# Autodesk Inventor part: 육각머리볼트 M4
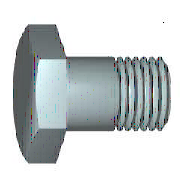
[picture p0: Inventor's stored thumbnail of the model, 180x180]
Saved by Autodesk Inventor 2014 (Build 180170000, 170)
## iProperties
IsCustomPart: 1
Created: 2012-02
Part Number: 육각머리볼트 M4
Material: 강철, 연강
Description: 6각 머리 볼트 및 6각 머리 나사
Document SubType Name: Modeling
Standard: KS B 1002
Designer: mduedu
Standards Organization: KS
Language: ko-KR
Size Designation: A + B M4 x 16
Categories: <MemberInstance><Categories><Category DisplayName="조임쇠" InternalName="e4da775c-781d-43d5-af7c-5136215cf5a6" Mnemonic="FSTN"><Category DisplayName="볼트" InternalN
Density: 7.86 g/cm^3
Appearance: 강철
Mass: 2.45486 g
Surface Area: 3.4613 cm^2
Volume: 0.312323 cm^3
Author: mduedu
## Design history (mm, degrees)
sketch "스케치1"
  geometry: L1 (0, 2.94)-(0, 2); L2 (2.1, 2)-(16, 2); L3 (16, 2)-(16, 0); L4 (16, 0)-(-0.4, 0); L5 (-3.68, 0)-(19.28, 0) reference; L6 (-0.4, 0)-(-0.4, 2.94); L7 (-0.4, 2.94)-(0, 2.94); L8 (2.1, 2)-(1.67, 2); L9 (1.67, 2)-(0, 2); L10 (0, -0.588)-(0, 3.528) reference
  constraints: 16 end point, 2 collinear, 2 perpendicular, 1 parallel
  dimensions: "d0" = 16 distance between parallel lines of L3 L1 (= NLG); "d1" = 13.9 distance from line of L2.start L3 (= GEL); "d2" = 4 diameter of L2 L4 (= GD); "d9" = 0.4001 distance between parallel lines of L6 L1 (computed from SD); "d10" = 5.88 diameter of L7 L4 (= SD2); "d13" = 0.42952 distance of L2.start L8.end (computed from GAL); "d14" = 4 diameter of L9 L4 (= BDM)
revolve "본체" sketch "스케치1" stored, may be unused: angle "d12" = 90 deg
sketch "스케치2"
  geometry: L1 (0, 4.041)-(3.5, 2.021); L2 (3.5, 2.021)-(3.5, -2.021); L3 (3.5, -2.021)-(0, -4.041); L4 (0, -4.041)-(-3.5, -2.021); L5 (-3.5, -2.021)-(-3.5, 2.021); L6 (-3.5, 2.021)-(0, 4.041); 2 further points
  constraints: 12 end point, 1 coincident, 1 vertical, 11 other
  dimensions: "d11" = 7 distance between parallel lines of L5 L2 (= SW)
extrude "머리" join sketch "스케치2" distance "d3" = 2.4 (= KOH - SD); taper "d4" = 0 deg
sketch "스케치4"
  geometry: L1 (-2.8, 3.5)-(-2.8, 4.041); L2 (-2.8, 4.041)-(-2.487, 4.041); L3 (-2.487, 4.041)-(-2.8, 3.5); L4 (-3.28, 0)-(0.08, 0) reference; L5 (-0.4, 4.041)-(-2.8, 4.041) reference; L6 (-2.8, 2.021)-(-2.8, 4.041) reference
  constraints: 6 end point, 2 collinear, 1 perpendicular, 1 vertical
  dimensions: "d5" = 30 deg angle of L3 L1 (= ANG1); "d19" = 7 diameter of L1.start L4 (= SW0)
revolve "모따기1" sketch "스케치4" stored, may be unused: angle "d21" = 90 deg
workplane "Work Plane1"
body "Solid1"
feature "스레드" dims "d15" = 13.9 (= GEL), "d16" = 0
chamfer "모따기2" distance "d6" = 0.42941 (= -0.5 x SPD + 0.5 x GD); stored, may be unused: second distance "d7" = 0.42952 (computed from GUL), angle "d55" = 45 deg
other parameters: "NLG" = 16 [user parameter; used in 1 equation term], "GD" = 4 (= NND) [user parameter; used in 2 equation terms], "BDM" = 4 (= NND) [user parameter; used in 1 equation term], "KOH" = 2.8 [user parameter; used in 1 equation term], "GEL" = 13.9 [user parameter; used in 2 equation terms], "SW" = 7 [user parameter; used in 3 equation terms], "SW0" = 7 (= SW) [user parameter; used in 1 equation term], "SPD" = 3.14117 (= NND - 1.2269 x PTC) [user parameter; used in 1 equation term], "SD2" = 5.88 (= SDH) [user parameter; used in 1 equation term], "SD" = 0.4 [user parameter; used in 2 equation terms], "ANG1" = 30 deg [user parameter; used in 1 equation term], "GAL" = 0.42941 (= 0.61345 x PTC) [user parameter; used in 1 equation term], "GUL" = 0.42941 (= 0.61345 x PTC) [user parameter; used in 1 equation term], "d8" = 0, "RR" = 0.2 [user parameter], "d57" = 0, "d58" = 0, "TPU" = 14.28571 (computed from PTC) [user parameter], "GD1" = 3.14117 (= THREADDIA - 1.2269 x PTC) [user parameter], "THREADDIA" = 4 [user parameter; used in 1 equation term], "SDH" = 5.88 [user parameter; used in 1 equation term], "SDHG" = 2.1 [user parameter], "TOA" = 30 deg [user parameter], "PTC" = 0.7 [user parameter; used in 5 equation terms], "NND" = 4 [user parameter; used in 3 equation terms], "E0" = 8.085 (= 1.155 x SW) [user parameter]
